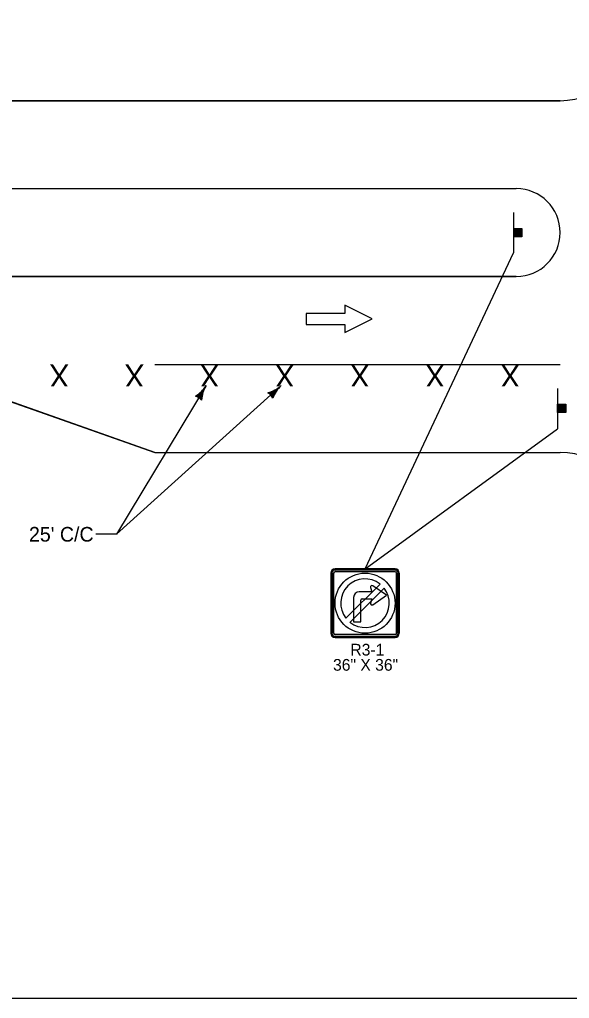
# Model space of a CAD drawing. Extents: x 10133 to 81668, y 7924 to 11018.
# Drawn here: x 10801 to 11553, y 7924 to 9260 of the extents above; entities that cross this region are included whole.
import ezdxf

# ---------------------------------------------------------------- set-up
doc = ezdxf.new("R2010")
doc.units = 0
for name, color, linetype in [('dsnStdBlock', 7, 'Continuous'), ('dsnStdBlockModified', 7, 'Continuous'), ('dsnstdModifiedBlock', 7, 'Continuous')]:
    doc.layers.add(name, color=color, linetype=linetype)

msp = doc.modelspace()

# ---------------------------------------------------------------- linework, layer by layer
at = {"layer": 'dsnStdBlock'}
for p, q in [((11476.4, 8996.6), (11476.4, 8941.6)), ((11477.2, 8963.7), (11477.2, 8974.9)), ((11477.8, 8974.9), (11477.8, 8963.7)), ((11478.3, 8963.7), (11478.3, 8974.9)), ((11478.8, 8974.9), (11478.8, 8963.7)), ((11479.2, 8963.7), (11479.2, 8974.9)), ((11479.7, 8974.9), (11479.7, 8963.7)), ((11480.3, 8963.7), (11480.3, 8974.9)), ((11480.8, 8974.9), (11480.8, 8963.7)), ((11481.3, 8963.7), (11481.3, 8974.9)), ((11481.9, 8974.9), (11481.9, 8963.7)), ((11482.7, 8963.7), (11482.7, 8974.9)), ((11483.5, 8974.9), (11483.5, 8963.7)), ((11484, 8963.7), (11483.9, 8974.9)), ((11484.8, 8974.9), (11484.8, 8963.7)), ((11485.3, 8963.7), (11485.3, 8974.9)), ((11485.9, 8974.9), (11485.9, 8963.7)), ((11486.3, 8963.7), (11486.3, 8974.9)), ((11487, 8974.9), (11487, 8963.7)), ((11056.2, 8760.4), (11046.3, 8744)), ((11056.2, 8760.4), (11051.2, 8752.1)), ((11158.9, 8760.4), (11144.6, 8747.5)), ((11158.9, 8760.4), (11151.7, 8753.9)), ((11536.4, 8756.6), (11536.4, 8701.6)), ((11537.2, 8723.7), (11537.2, 8734.9)), ((11537.8, 8734.9), (11537.8, 8723.7)), ((11538.3, 8723.7), (11538.3, 8734.9)), ((11538.8, 8734.9), (11538.8, 8723.7)), ((11539.2, 8723.7), (11539.2, 8734.9)), ((11539.7, 8734.9), (11539.7, 8723.7)), ((11540.3, 8723.7), (11540.3, 8734.9)), ((11540.8, 8734.9), (11540.8, 8723.7)), ((11541.3, 8723.7), (11541.3, 8734.9)), ((11541.9, 8734.9), (11541.9, 8723.7)), ((11542.7, 8723.7), (11542.7, 8734.9)), ((11543.5, 8734.9), (11543.5, 8723.7)), ((11544, 8723.7), (11543.9, 8734.9)), ((11544.8, 8734.9), (11544.8, 8723.7)), ((11545.3, 8723.7), (11545.3, 8734.9)), ((11545.9, 8734.9), (11545.9, 8723.7)), ((11546.3, 8723.7), (11546.3, 8734.9)), ((11547, 8734.9), (11547, 8723.7))]:
    msp.add_line(p, q, dxfattribs=at)
for points in [[(11540, 9149.3), (10332.5, 9149.3), (10332.5, 9029.3), (11480, 9029.3)], [(11480, 8909.3), (10332.5, 8909.3), (10332.5, 8789.3), (10644.7, 8789.3), (10986.3, 8669.3), (11540, 8669.3)], [(11245.7, 8844), (11245.7, 8832.8), (11283.2, 8851.5), (11245.7, 8870.3), (11245.7, 8859), (11193.2, 8859), (11193.2, 8844), (11245.7, 8844)], [(11049.5, 8742.5), (11046.8, 8744.9), (11043.3, 8746.2), (11047.3, 8748.8), (11052.2, 8753.8), (11049.9, 8746.7), (11049.4, 8743.2), (11047.2, 8745.5), (11045, 8746.4), (11047.6, 8748.2), (11050.4, 8750.9), (11049.3, 8746.9), (11048.9, 8744.7), (11046.5, 8746.6), (11048.9, 8748.4), (11048.4, 8746.2), (11047.4, 8746.7), (11048.3, 8747.4)], [(11147.3, 8745.2), (11145.4, 8748.3), (11142.4, 8750.5), (11147, 8751.8), (11153.1, 8755.2), (11148.8, 8749.1), (11147.4, 8745.9), (11145.9, 8748.7), (11144.1, 8750.3), (11147.1, 8751.1), (11150.6, 8753), (11148.4, 8749.4), (11147.3, 8747.5), (11145.5, 8750), (11148.4, 8751), (11147.2, 8749), (11146.5, 8749.8), (11147.5, 8750.2)]]:
    msp.add_lwpolyline(points, dxfattribs=at)
for points in [[(11476.6, 8963.7), (11476.6, 8975), (11487.8, 8975), (11487.8, 8963.7)], [(11536.6, 8723.7), (11536.6, 8735), (11547.8, 8735), (11547.8, 8723.7)]]:
    msp.add_lwpolyline(points, close=True, dxfattribs=at)
for centre, radius, start, end in [((11540, 9249.3), 100, 270, 0), ((11480, 8969.3), 60, 270, 90), ((11019.8, 8782.4), 42.5, 300.7705, 328.8429), ((11092.6, 8738.4), 42.5, 148.8429, 176.9154), ((11130.4, 8792), 42.5, 283.9525, 312.025), ((11187.3, 8728.8), 42.5, 132.025, 160.0975), ((11037.8, 8729.9), 16.4, 41.1096, 76.5763), ((11132.4, 8736.5), 16.4, 24.2917, 59.7584), ((11540, 8569.3), 100, 0, 90)]:
    msp.add_arc(centre, radius, start, end, dxfattribs=at)
at = {"layer": 'dsnStdBlockModified'}
for p, q in [((11273.4, 8510.4), (11476.4, 8941.6)), ((11056.2, 8760.4), (10933.6, 8557.5)), ((10933.6, 8557.5), (11158.9, 8760.4)), ((11273.4, 8510.4), (11536.4, 8701.6)), ((10933.6, 8557.5), (10905.4, 8557.5)), ((11314.4, 8510.4), (11232.4, 8510.4)), ((11226.5, 8504.5), (11226.5, 8422.5)), ((11228.2, 8504.5), (11228.2, 8422.5)), ((11228.2, 8504.5), (11228.2, 8422.5)), ((11230.4, 8504.5), (11230.4, 8422.5)), ((11230.4, 8422.5), (11230.4, 8504.5)), ((11314.4, 8508.8), (11232.4, 8508.8)), ((11314.4, 8508.8), (11232.4, 8508.8)), ((11314.4, 8506.5), (11232.4, 8506.5)), ((11232.4, 8506.5), (11314.4, 8506.5)), ((11316.4, 8422.5), (11316.4, 8504.5)), ((11316.4, 8504.5), (11316.4, 8422.5)), ((11318.7, 8422.5), (11318.7, 8504.5)), ((11318.7, 8422.5), (11318.7, 8504.5)), ((11320.3, 8422.5), (11320.3, 8504.5)), ((11247.3, 8442.9), (11294, 8489.6)), ((11299.5, 8484.1), (11252.9, 8437.4)), ((11232.4, 8420.5), (11314.4, 8420.5)), ((11314.4, 8420.5), (11232.4, 8420.5)), ((11232.4, 8418.2), (11314.4, 8418.2)), ((11232.4, 8418.2), (11314.4, 8418.2)), ((11232.4, 8416.6), (11314.4, 8416.6))]:
    msp.add_line(p, q, dxfattribs=at)
for points in [[(11281, 8484.9), (11282.9, 8479.1), (11265.6, 8479.1)], [(11284, 8461.4), (11302.7, 8474.2), (11284, 8487.1)], [(11257.8, 8471.3), (11257.8, 8438.1), (11267.6, 8438.1), (11267.6, 8467.4)], [(11269.5, 8469.4), (11282.9, 8469.4), (11281, 8463.6)]]:
    msp.add_lwpolyline(points, dxfattribs=at)
msp.add_circle((11273.4, 8463.5), 41, dxfattribs=at)
for centre, radius, start, end in [((11232.4, 8504.5), 5.86, 90, 180), ((11314.4, 8504.5), 5.86, 0, 90), ((11232.4, 8504.5), 4.23, 90, 180), ((11232.4, 8504.5), 4.23, 90, 180), ((11232.4, 8504.5), 1.95, 90, 180), ((11232.4, 8504.5), 1.95, 90, 180), ((11314.4, 8504.5), 4.23, 0, 90), ((11314.4, 8504.5), 4.23, 0, 90), ((11314.4, 8504.5), 1.95, 0, 90), ((11314.4, 8504.5), 1.95, 0, 90), ((11273.4, 8463.5), 33.2, 51.7563, 218.2437), ((11273.4, 8463.5), 33.2, 231.7563, 38.2437), ((11282.9, 8485.5), 1.95, 55.5945, 197.9164), ((11265.6, 8471.3), 7.81, 90, 180), ((11269.5, 8467.4), 1.95, 90, 180), ((11282.9, 8463), 1.95, 162.0836, 304.4055), ((11232.4, 8422.5), 5.86, 180, 270), ((11232.4, 8422.5), 4.23, 180, 270), ((11232.4, 8422.5), 4.23, 180, 270), ((11232.4, 8422.5), 1.95, 180, 270), ((11232.4, 8422.5), 1.95, 180, 270), ((11314.4, 8422.5), 1.95, 270, 0), ((11314.4, 8422.5), 4.23, 270, 0), ((11314.4, 8422.5), 5.86, 270, 0), ((11314.4, 8422.5), 4.23, 270, 0), ((11314.4, 8422.5), 1.95, 270, 0)]:
    msp.add_arc(centre, radius, start, end, dxfattribs=at)
at = {"layer": 'dsnstdModifiedBlock'}
for p, q in [((10332.5, 9149.3), (11540, 9149.3)), ((10332.5, 9029.3), (11480, 9029.3)), ((10332.5, 8909.3), (11480, 8909.3)), ((10986.3, 8669.3), (10644.7, 8789.3)), ((10986.3, 8789.3), (11540, 8789.3)), ((10986.3, 8669.3), (11540, 8669.3))]:
    msp.add_line(p, q, dxfattribs=at)
msp.add_lwpolyline([(10132.5, 9944), (13267.5, 9944), (13267.5, 7924), (10132.5, 7924)], close=True, dxfattribs=at)
for centre, radius, start, end in [((11540, 9249.3), 100, 270, 0), ((11480, 8969.3), 60, 270, 90), ((11540, 8569.3), 100, 0, 90)]:
    msp.add_arc(centre, radius, start, end, dxfattribs=at)

# ---------------------------------------------------------------- texts
at = {"layer": 'dsnStdBlock'}
for p in [(10869, 8789.3), (10971.7, 8789.3), (11074.4, 8789.3), (11177.1, 8789.3), (11279.8, 8789.3), (11382.5, 8789.3), (11485.2, 8789.3)]:
    msp.add_text('X', height=30, rotation=180, dxfattribs=at).set_placement(p)
at = {"layer": 'dsnStdBlockModified'}
for s, height, p in [("25' C/C", 20, (10814.2, 8547.5)), ('R3-1', 16, (11253.4, 8392)), ('36" X 36"', 16, (11229.7, 8371.3))]:
    msp.add_text(s, height=height, dxfattribs=at).set_placement(p)

doc.saveas('drawing.dxf')
